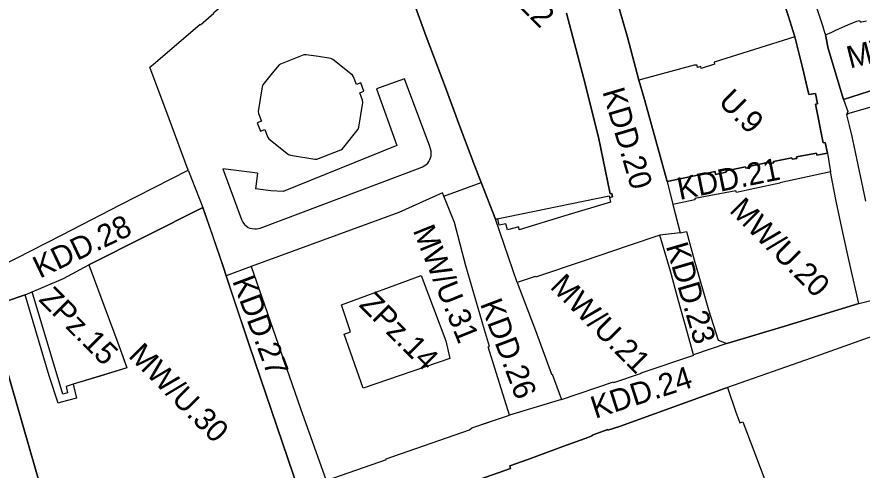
# Model space of a CAD drawing. Extents: x 7423835 to 7425280, y 5546086 to 5547600.
# Drawn here: x 7424365.2 to 7424593.5, y 5546605 to 5546727.5 of the extents above; entities that cross this region are included whole.
import ezdxf

# ---------------------------------------------------------------- set-up
doc = ezdxf.new("R2010")
doc.units = 0
for name, color, linetype in [('linie rozgraniczające', 7, 'Continuous'), ('nieprzekraczalne linie zabudowy', 7, 'Continuous'), ('obowiazujace linie zabudowy', 7, 'Continuous'), ('przeznaczenia terenów', 7, 'Continuous')]:
    doc.layers.add(name, color=color, linetype=linetype)

msp = doc.modelspace()

# ---------------------------------------------------------------- linework, layer by layer
at = {"layer": 'linie rozgraniczające'}
for p, q in [((7424584.14, 5546690.7), (7424584.96, 5546685.65)), ((7424411.49, 5546686.07), (7424415.44, 5546675.99)), ((7424480.47, 5546679.05), (7424490.62, 5546682.75)), ((7424540.84, 5546682.97), (7424542.35, 5546676.82)), ((7424384.62, 5546660.5), (7424415.44, 5546675.99)), ((7424500.31, 5546655.7), (7424494.44, 5546672.79)), ((7424544.38, 5546669.11), (7424538.82, 5546668.52)), ((7424428.5, 5546660.01), (7424421.75, 5546657.53)), ((7424592.61, 5546650.05), (7424600.35, 5546651.93)), ((7424556.96, 5546639.21), (7424548, 5546636.2)), ((7424512.26, 5546624.1), (7424498.22, 5546619.84))]:
    msp.add_line(p, q, dxfattribs=at)
for points in [[(7424546.87, 5546840.16), (7424553.07, 5546822.35), (7424558.38, 5546806.12), (7424562.73, 5546793.62), (7424565.74, 5546781.7), (7424566.26, 5546779.13), (7424567.08, 5546775.74), (7424567.21, 5546775.74), (7424572.61, 5546757.78), (7424579.36, 5546736.66), (7424581.27, 5546729.79), (7424582.77, 5546725.18), (7424583.4, 5546722.97), (7424583.5, 5546722.97), (7424583.6, 5546722.64)], [(7424549.68, 5546806.67), (7424550.18, 5546806.02), (7424550.86, 5546803.72), (7424550.75, 5546803.67), (7424553.78, 5546793.71), (7424553.9, 5546793.74), (7424555.07, 5546789.88), (7424556.24, 5546786.02), (7424556.8, 5546784.13), (7424557.79, 5546780.85), (7424558.79, 5546777.57), (7424559.11, 5546776.59), (7424559.43, 5546775.61), (7424560.29, 5546772.82), (7424561.14, 5546770.02), (7424564.03, 5546759.83), (7424566.48, 5546751.02), (7424568.78, 5546743.12), (7424571.01, 5546735.66), (7424573.5, 5546727.81), (7424575.32, 5546722.07)], [(7424533.19, 5546710.4), (7424530.14, 5546721.98), (7424526.01, 5546736.37), (7424523.85, 5546745.11), (7424521.65, 5546753.29), (7424517.7, 5546767.71), (7424513.85, 5546780.93), (7424512.66, 5546784.92), (7424530.31, 5546796.82)], [(7424411.49, 5546686.07), (7424406.27, 5546699.92), (7424401.12, 5546713.85), (7424401.96, 5546714.58), (7424414.65, 5546725.53), (7424414.8, 5546725.36), (7424418.35, 5546728.48), (7424418.27, 5546728.6), (7424433.52, 5546741.82), (7424433.64, 5546741.73), (7424437.27, 5546744.83), (7424451.13, 5546756.99)], [(7424513.61, 5546728.52), (7424518.32, 5546710.75), (7424522.3, 5546694.97), (7424525.46, 5546679.64), (7424525.87, 5546679.73), (7424526.07, 5546678.85), (7424525.27, 5546678.7), (7424525.54, 5546677.44), (7424513.2, 5546673.71), (7424500.86, 5546669.97), (7424500.73, 5546670.72), (7424497.68, 5546669.98), (7424497.27, 5546671.57), (7424495.5, 5546671.19), (7424495.06, 5546672.92), (7424494.44, 5546672.79), (7424488.92, 5546687.19), (7424484.85, 5546697.87), (7424480.95, 5546708.39), (7424475.76, 5546722.19), (7424471.03, 5546735.11)], [(7424597.47, 5546708.02), (7424588.52, 5546705.15), (7424584.37, 5546718.9), (7424583.6, 5546722.64), (7424585.33, 5546723.31), (7424586.58, 5546723.96), (7424589.66, 5546725.3), (7424592.09, 5546726.29), (7424592.81, 5546726.52), (7424592.97, 5546726.15), (7424593.38, 5546726.12), (7424594.73, 5546726.44)], [(7424575.32, 5546722.07), (7424553.53, 5546715.28), (7424553.66, 5546714.75), (7424550.03, 5546713.52), (7424549.9, 5546714.07), (7424549.02, 5546713.83), (7424548.91, 5546714.42), (7424548.1, 5546714.4), (7424533.19, 5546710.4)], [(7424575.32, 5546722.07), (7424577.37, 5546713.84), (7424579.12, 5546706.48), (7424580.9, 5546706.78), (7424581.44, 5546704.02), (7424580.94, 5546703.87), (7424583, 5546693.42), (7424583, 5546693.41), (7424583.55, 5546693.53), (7424584.14, 5546690.7)], [(7424584.14, 5546690.7), (7424581.3, 5546690.16), (7424581.21, 5546690.66), (7424575.78, 5546689.64), (7424575.85, 5546689.26), (7424574.6, 5546689.02), (7424574.54, 5546689.38), (7424569.6, 5546688.42), (7424569.66, 5546688.06), (7424568.4, 5546687.82), (7424568.33, 5546688.19), (7424563.33, 5546687.19), (7424563.38, 5546686.83), (7424562.12, 5546686.6), (7424562.05, 5546686.97), (7424556.77, 5546685.92), (7424556.81, 5546685.48), (7424553.94, 5546684.9), (7424553.8, 5546685.74), (7424540.84, 5546682.97), (7424534.7, 5546705.2), (7424533.19, 5546710.4)], [(7424588.52, 5546705.15), (7424589.62, 5546701.93), (7424589.31, 5546701.02)], [(7424602.82, 5546705.09), (7424589.91, 5546701.38), (7424589.31, 5546701.02), (7424590.04, 5546698.11), (7424590.69, 5546695.15), (7424591.23, 5546692.64), (7424594.43, 5546677.7)], [(7424356.67, 5546658.07), (7424377.38, 5546668.63), (7424393.12, 5546676.67), (7424411.49, 5546686.07)], [(7424592.61, 5546650.05), (7424590.16, 5546660.7), (7424588.34, 5546669.23), (7424586.47, 5546677.69), (7424584.96, 5546685.65), (7424571.3, 5546682.68), (7424571.3, 5546682.58), (7424564.51, 5546681.07), (7424559.6, 5546680), (7424559.43, 5546680.5), (7424548.29, 5546678.41), (7424548.35, 5546678.04), (7424542.35, 5546676.82), (7424544.38, 5546669.11), (7424546.03, 5546669.53), (7424548.1, 5546661.82), (7424552.01, 5546648.3), (7424554.58, 5546640.17), (7424556.96, 5546639.21)], [(7424498.22, 5546619.84), (7424492.5, 5546638.34), (7424492.84, 5546638.45), (7424491.5, 5546642.95), (7424486.43, 5546660.24), (7424483.37, 5546671.92), (7424480.11, 5546679.93), (7424468.32, 5546674.65), (7424455.33, 5546669.86), (7424428.5, 5546660.01), (7424437.17, 5546634.91), (7424441.77, 5546621.66), (7424448.69, 5546602.18), (7424464.99, 5546607.91), (7424464.93, 5546608.08), (7424487.47, 5546615.94)], [(7424415.44, 5546675.99), (7424420.93, 5546660.04), (7424421.75, 5546657.53), (7424423.79, 5546651.25), (7424427.88, 5546638.9), (7424441.46, 5546599.12), (7424429.54, 5546594.89), (7424419.97, 5546592.1), (7424408.6, 5546588.75), (7424395.96, 5546584.68), (7424377.65, 5546579.36), (7424357.5, 5546649.05), (7424367.44, 5546652.38), (7424372.88, 5546654.73), (7424377.74, 5546656.83), (7424384.62, 5546660.5)], [(7424548, 5546636.2), (7424546.12, 5546642.78), (7424543.87, 5546650.76), (7424541.71, 5546658.77), (7424538.82, 5546668.52), (7424530.3, 5546665.61), (7424518.46, 5546661.56), (7424505.27, 5546657.12), (7424505.2, 5546657.32), (7424500.31, 5546655.7), (7424505.25, 5546642.78), (7424509.61, 5546630.91), (7424509.75, 5546630.96), (7424512.26, 5546624.1)], [(7424384.62, 5546660.5), (7424392.68, 5546638.72), (7424394.91, 5546632.63), (7424380.38, 5546628.23), (7424378.46, 5546627.64), (7424378.87, 5546625.88), (7424377.62, 5546625.55), (7424369.3, 5546653.18)], [(7424592.61, 5546650.05), (7424572.63, 5546643.95), (7424556.96, 5546639.21)], [(7424604.68, 5546613.08), (7424597.85, 5546636.65), (7424599.01, 5546637.03), (7424597.65, 5546641.67), (7424579.79, 5546635.27), (7424557.12, 5546627.37)], [(7424512.26, 5546624.1), (7424526.35, 5546628.85), (7424526.4, 5546628.68), (7424533.87, 5546631.23), (7424533.85, 5546631.33), (7424548.04, 5546636.06), (7424548, 5546636.2)], [(7424479.78, 5546598.91), (7424498.49, 5546605.47), (7424498.33, 5546606.18), (7424503.24, 5546607.92), (7424511.18, 5546610.86), (7424512.65, 5546611.4), (7424518.71, 5546613.58), (7424518.71, 5546613.58), (7424520.6, 5546614.24), (7424520.56, 5546614.42), (7424524.78, 5546615.97), (7424524.85, 5546615.78), (7424528, 5546616.82), (7424556.34, 5546627.1), (7424557.12, 5546627.37)], [(7424557.12, 5546627.37), (7424559.4, 5546620.71), (7424560.48, 5546617.76), (7424561.25, 5546618.02), (7424567.94, 5546600.51), (7424555.92, 5546596.35)], [(7424487.47, 5546615.94), (7424488.08, 5546616.43), (7424498.22, 5546619.84)]]:
    msp.add_lwpolyline(points, dxfattribs=at)
msp.add_lwpolyline([(7424474.38, 5546657.59), (7424481.07, 5546639.93), (7424482.1, 5546635.14), (7424458.75, 5546627.15), (7424453.56, 5546641.77), (7424455.3, 5546642.35), (7424452.84, 5546649.64)], close=True, dxfattribs=at)
at = {"layer": 'nieprzekraczalne linie zabudowy'}
for p, q in [((7424469.85, 5546710.76), (7424462.35, 5546708.07)), ((7424462.35, 5546708.07), (7424467.86, 5546692.7)), ((7424467.86, 5546692.7), (7424437.14, 5546680.26)), ((7424430.17, 5546685.29), (7424420.79, 5546686.44)), ((7424430.17, 5546685.29), (7424429.64, 5546681.03))]:
    msp.add_line(p, q, dxfattribs=at)
msp.add_lwpolyline([(7424450.5, 5546715.99), (7424450, 5546716.21), (7424446.65, 5546716.74), (7424443.3, 5546717.27), (7424442.72, 5546717.21), (7424436.38, 5546714.73), (7424436.15, 5546714.57), (7424435.92, 5546714.41), (7424433.79, 5546711.78), (7424431.66, 5546709.14), (7424431.54, 5546708.88), (7424431.42, 5546708.62), (7424430.9, 5546705.28), (7424430.38, 5546701.93), (7424430.44, 5546701.38), (7424431.24, 5546699.33), (7424430.1, 5546698.88), (7424431, 5546696.63), (7424432.13, 5546697.06), (7424432.91, 5546695.06), (7424433.24, 5546694.54), (7424438.53, 5546690.31), (7424439.05, 5546690.08), (7424445.68, 5546689.05), (7424446.24, 5546689.05), (7424452.67, 5546691.54), (7424453.12, 5546691.87), (7424457.38, 5546697.16), (7424457.58, 5546697.67), (7424458.65, 5546704.38), (7424458.58, 5546704.95), (7424457.8, 5546706.96), (7424458.88, 5546707.38), (7424458.07, 5546709.67), (7424456.92, 5546709.23), (7424456.13, 5546711.27), (7424455.8, 5546711.72)], close=True, dxfattribs=at)
for points in [[(7424420.79, 5546686.44), (7424425.86, 5546672.74), (7424426.19, 5546672.02), (7424426.7, 5546671.36), (7424427.12, 5546670.98), (7424427.65, 5546670.61), (7424428.12, 5546670.43), (7424428.72, 5546670.27), (7424429.42, 5546670.17), (7424429.88, 5546670.19), (7424430.42, 5546670.27), (7424430.94, 5546670.43), (7424474.15, 5546686.7), (7424474.78, 5546686.97), (7424475.61, 5546687.48), (7424476.16, 5546687.99), (7424476.49, 5546688.45), (7424476.75, 5546688.93), (7424476.92, 5546689.37), (7424477.06, 5546689.86), (7424477.09, 5546690.14), (7424477.08, 5546691.21), (7424476.75, 5546692.47), (7424469.85, 5546710.76)], [(7424437.14, 5546680.26), (7424433.82, 5546680.51), (7424429.64, 5546681.03)]]:
    msp.add_lwpolyline(points, dxfattribs=at)
at = {"layer": 'obowiazujace linie zabudowy'}
msp.add_line((7424415.44, 5546675.99), (7424384.62, 5546660.5), dxfattribs=at)
for points in [[(7424575.32, 5546722.07), (7424573.5, 5546727.81), (7424571.01, 5546735.66), (7424568.78, 5546743.12), (7424566.48, 5546751.02), (7424564.03, 5546759.83), (7424561.14, 5546770.02), (7424560.29, 5546772.82), (7424559.43, 5546775.61), (7424559.11, 5546776.59), (7424558.79, 5546777.57), (7424557.79, 5546780.85), (7424556.8, 5546784.13), (7424556.24, 5546786.02), (7424555.07, 5546789.88), (7424553.9, 5546793.74), (7424553.78, 5546793.71), (7424550.75, 5546803.67), (7424550.86, 5546803.72), (7424550.18, 5546806.02), (7424549.68, 5546806.67)], [(7424530.31, 5546796.82), (7424512.66, 5546784.92), (7424513.85, 5546780.93), (7424517.7, 5546767.71), (7424521.65, 5546753.29), (7424523.85, 5546745.11), (7424526.01, 5546736.37), (7424530.14, 5546721.98), (7424533.19, 5546710.4)], [(7424411.49, 5546686.07), (7424406.27, 5546699.92), (7424401.12, 5546713.85), (7424401.96, 5546714.58), (7424414.65, 5546725.53), (7424414.8, 5546725.36), (7424418.35, 5546728.48), (7424418.27, 5546728.6), (7424433.52, 5546741.82), (7424433.64, 5546741.73), (7424437.27, 5546744.83), (7424451.13, 5546756.99)], [(7424466.37, 5546747.65), (7424466.51, 5546747.7), (7424471.03, 5546735.11), (7424475.76, 5546722.19), (7424480.95, 5546708.39), (7424484.85, 5546697.87), (7424488.92, 5546687.19), (7424490.62, 5546682.75)], [(7424490.62, 5546682.75), (7424494.44, 5546672.79), (7424525.19, 5546679.15), (7424525.27, 5546678.7), (7424526.07, 5546678.85), (7424525.87, 5546679.73), (7424525.46, 5546679.64), (7424522.3, 5546694.97), (7424518.32, 5546710.75), (7424513.61, 5546728.52)], [(7424584.14, 5546690.7), (7424583.55, 5546693.53), (7424583, 5546693.41), (7424583, 5546693.42), (7424580.94, 5546703.87), (7424581.44, 5546704.02), (7424580.9, 5546706.78), (7424579.12, 5546706.48), (7424577.37, 5546713.84), (7424575.32, 5546722.07)], [(7424583.6, 5546722.64), (7424584.37, 5546718.9), (7424588.52, 5546705.15), (7424597.47, 5546708.02), (7424597.4, 5546708.32), (7424605.17, 5546710.42), (7424614.94, 5546713.4), (7424626.77, 5546717.3)], [(7424533.19, 5546710.4), (7424534.7, 5546705.2), (7424540.84, 5546682.97), (7424553.8, 5546685.74), (7424553.94, 5546684.9), (7424556.81, 5546685.48), (7424556.77, 5546685.92), (7424562.05, 5546686.97), (7424562.12, 5546686.6), (7424563.38, 5546686.83), (7424563.33, 5546687.19), (7424568.33, 5546688.19), (7424568.4, 5546687.82), (7424569.66, 5546688.06), (7424569.6, 5546688.42), (7424574.54, 5546689.38), (7424574.6, 5546689.02), (7424575.85, 5546689.26), (7424575.78, 5546689.64), (7424581.21, 5546690.66), (7424581.3, 5546690.16), (7424584.14, 5546690.7)], [(7424602.82, 5546705.09), (7424589.91, 5546701.38), (7424589.31, 5546701.02), (7424590.04, 5546698.11), (7424590.69, 5546695.15), (7424591.23, 5546692.64), (7424594.43, 5546677.7)], [(7424356.67, 5546658.07), (7424377.38, 5546668.63), (7424393.12, 5546676.67), (7424411.49, 5546686.07)], [(7424592.61, 5546650.05), (7424590.16, 5546660.7), (7424588.34, 5546669.23), (7424586.47, 5546677.69), (7424584.96, 5546685.65), (7424571.3, 5546682.68), (7424571.3, 5546682.58), (7424564.51, 5546681.07), (7424559.6, 5546680), (7424559.43, 5546680.5), (7424548.29, 5546678.41), (7424548.35, 5546678.04), (7424542.35, 5546676.82), (7424544.38, 5546669.11), (7424546.03, 5546669.53), (7424548.1, 5546661.82), (7424552.01, 5546648.3), (7424554.58, 5546640.17), (7424556.96, 5546639.21)], [(7424498.22, 5546619.84), (7424492.5, 5546638.34), (7424492.84, 5546638.45), (7424491.5, 5546642.95), (7424486.43, 5546660.24), (7424483.37, 5546671.92), (7424480.11, 5546679.93), (7424468.32, 5546674.65), (7424455.33, 5546669.86), (7424428.5, 5546660.01), (7424437.17, 5546634.91), (7424441.77, 5546621.66), (7424448.69, 5546602.18), (7424464.99, 5546607.91), (7424464.93, 5546608.08), (7424487.47, 5546615.94)], [(7424498.22, 5546619.84), (7424492.5, 5546638.34), (7424492.84, 5546638.45), (7424491.5, 5546642.95), (7424486.43, 5546660.24), (7424483.37, 5546671.92), (7424480.47, 5546679.05)], [(7424421.71, 5546657.52), (7424420.93, 5546660.04), (7424418.19, 5546668.01), (7424415.44, 5546675.99)], [(7424548, 5546636.2), (7424546.12, 5546642.78), (7424543.87, 5546650.76), (7424541.71, 5546658.77), (7424538.82, 5546668.52), (7424530.3, 5546665.61), (7424518.46, 5546661.56), (7424505.27, 5546657.12), (7424505.2, 5546657.32), (7424500.31, 5546655.7), (7424505.25, 5546642.78), (7424509.61, 5546630.91), (7424509.75, 5546630.96), (7424512.26, 5546624.1)], [(7424384.62, 5546660.5), (7424388.65, 5546649.61), (7424392.68, 5546638.72), (7424393.79, 5546635.68), (7424394.91, 5546632.63), (7424387.65, 5546630.43), (7424380.38, 5546628.23)], [(7424367.44, 5546652.38), (7424357.5, 5546649.05), (7424377.65, 5546579.36), (7424395.96, 5546584.68), (7424408.6, 5546588.75), (7424419.97, 5546592.1), (7424429.54, 5546594.89), (7424441.46, 5546599.12), (7424427.88, 5546638.9), (7424421.71, 5546657.52)], [(7424380.38, 5546628.23), (7424380.38, 5546628.23), (7424381.25, 5546624.44), (7424377.13, 5546623.35), (7424376.33, 5546623.11), (7424373.87, 5546630.48), (7424367.44, 5546652.38)], [(7424556.96, 5546639.21), (7424572.63, 5546643.95), (7424592.61, 5546650.05)], [(7424597.65, 5546641.67), (7424579.79, 5546635.27), (7424557.12, 5546627.37)], [(7424512.26, 5546624.1), (7424526.35, 5546628.85), (7424526.4, 5546628.68), (7424533.87, 5546631.23), (7424533.85, 5546631.33), (7424548.04, 5546636.06), (7424548, 5546636.2)], [(7424557.12, 5546627.37), (7424556.34, 5546627.1), (7424528, 5546616.82), (7424524.85, 5546615.78), (7424524.78, 5546615.97), (7424520.56, 5546614.42), (7424520.6, 5546614.24), (7424518.71, 5546613.58), (7424518.71, 5546613.58), (7424512.65, 5546611.4), (7424511.18, 5546610.86), (7424503.24, 5546607.92), (7424498.33, 5546606.18), (7424498.49, 5546605.47), (7424479.78, 5546598.91)], [(7424487.47, 5546615.94), (7424488.08, 5546616.43), (7424493.15, 5546618.13), (7424498.22, 5546619.84)]]:
    msp.add_lwpolyline(points, dxfattribs=at)

# ---------------------------------------------------------------- texts
at = {"layer": 'przeznaczenia terenów'}
for s, rotation, p in [('MW/U.22', 314.9764, (7424483.05, 5546747.82)), ('MW/U.14', 14.3097, (7424590.23, 5546713.5)), ('KDD.20', 286.4751, (7424523.29, 5546707.34)), ('U.9', 314.9764, (7424554.39, 5546704.31)), ('KDD.21', 11.5219, (7424544.22, 5546677.99)), ('MW/U.20', 314.9764, (7424557.42, 5546674.98)), ('KDD.28', 25.5466, (7424371.37, 5546656.72)), ('MW/U.31', 291.9946, (7424472.08, 5546669.81)), ('KDD.23', 286.3703, (7424540.42, 5546665.56)), ('MW/U.21', 314.9764, (7424508.97, 5546654.35)), ('KDD.27', 290.4779, (7424423.29, 5546656.16)), ('ZPz.15', 314.9764, (7424370.81, 5546650.89)), ('ZPz.14', 314.9764, (7424457.38, 5546649.48)), ('KDD.26', 290.6814, (7424490.23, 5546649.98)), ('MW/U.30', 314.9764, (7424395.04, 5546635.65)), ('KDD.24', 17.9431, (7424521.39, 5546618.88))]:
    msp.add_text(s, height=6, rotation=rotation, dxfattribs=at).set_placement(p)

doc.saveas('drawing.dxf')
